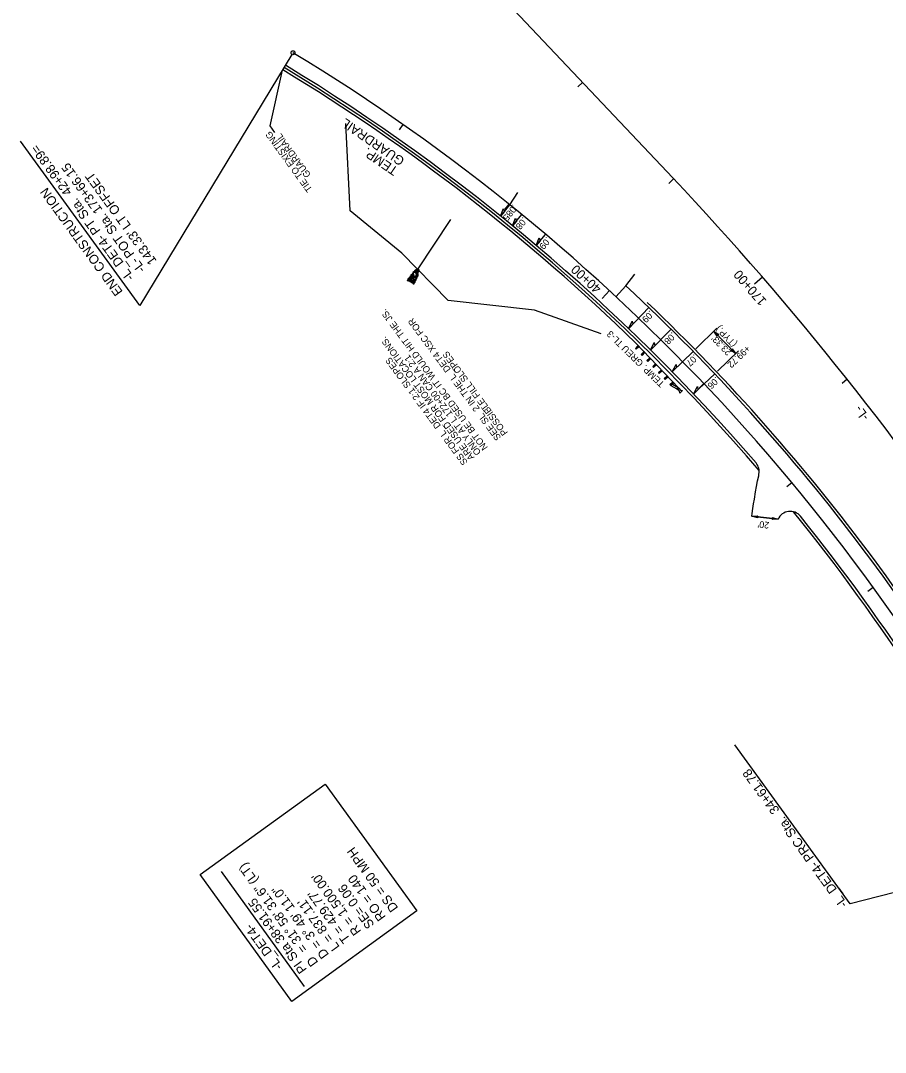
# Model space of a CAD drawing. Extents: x 473658 to 481584, y 489119 to 506230.
# Drawn here: x 474826 to 475478, y 502196 to 502974 of the extents above; entities that cross this region are included whole.
import ezdxf

# ---------------------------------------------------------------- set-up
doc = ezdxf.new("R2010")
doc.units = 0
for name, color, linetype in [('Exist Horizontal Alignment', 7, 'Continuous'), ('Prop Dimension', 7, 'Continuous'), ('Prop EOT', 7, 'Continuous'), ('Prop Guardrail', 7, 'Continuous'), ('Prop Guardrail Anchor Unit CELL', 7, 'Continuous'), ('Prop Horizontal Alignment', 7, 'Continuous'), ('Prop Horizontal Alignment Curve and Spiral Data', 7, 'Continuous'), ('Prop Horizontal Alignment Station Label', 7, 'Continuous'), ('Prop Horizontal Alignment Tick Label', 7, 'Continuous'), ('Prop Horizontal Alignment Tick Large', 7, 'Continuous'), ('Prop Horizontal Alignment Tick Small', 7, 'Continuous'), ('Prop Paved Shoulder', 7, 'Continuous'), ('Prop Superelevation  Arrow CELL', 7, 'Continuous'), ('Prop Superelevation Label', 7, 'Continuous'), ('Scratch_Level_3', 7, 'Continuous'), ('Scratch_Level_5', 7, 'Continuous'), ('Sheet Profile Grid Major CELL', 7, 'Continuous')]:
    doc.layers.add(name, color=color, linetype=linetype)

msp = doc.modelspace()

# ---------------------------------------------------------------- linework, layer by layer
at = {"layer": 'Exist Horizontal Alignment'}
for points in [[(475381.81, 502599.11), (475377.43, 502600.38), (475382.01, 502600.68), (475381.35, 502599.94)], [(475392.84, 502599.44), (475397.22, 502598.17), (475392.64, 502597.88), (475393.3, 502598.61)]]:
    msp.add_lwpolyline(points, close=True, dxfattribs=at)
at = {"layer": 'Prop Dimension'}
msp.add_line((475377.43, 502600.38), (475397.22, 502598.17), dxfattribs=at)
at = {"layer": 'Prop EOT'}
msp.add_line((475397.22, 502598.17), (475377.43, 502600.38), dxfattribs=at)
msp.add_lwpolyline([(475377.43, 502600.38), (475377.67, 502602.55), (475378.18, 502606.33), (475378.73, 502609.86), (475379.32, 502613.3), (475380.3, 502618.83), (475381.04, 502622.94), (475381.81, 502627), (475382.59, 502630.98), (475382.83, 502632.23)], dxfattribs=at)
for centre, radius, start, end in [((474253.94, 501667.1), 1489, 40.83118, 58.77708), ((474253.94, 501667.1), 1511, 26.80164, 47.10099), ((475373.01, 502634.11), 10, 349.13134, 40.83118), ((475406.36, 502594.11), 10, 38.81332, 156.02599), ((474253.94, 501667.1), 1489, 26.80164, 38.81332)]:
    msp.add_arc(centre, radius, start, end, dxfattribs=at)
at = {"layer": 'Prop Guardrail'}
msp.add_arc((474253.94, 501667.1), 1485, 45.75531, 58.77708, dxfattribs=at)
at = {"layer": 'Prop Guardrail Anchor Unit CELL'}
for p, q in [((475014.37, 502894.61), (475023.6, 502936.81)), ((475017.9, 502889.73), (475014.37, 502894.61)), ((475291.81, 502729.06), (475289.64, 502726.99)), ((475291.42, 502727.3), (475289.64, 502726.99)), ((475289.64, 502726.99), (475290.33, 502726.27)), ((475290.06, 502730.9), (475322.35, 502697.09)), ((475292.5, 502728.34), (475290.33, 502726.27)), ((475290.33, 502726.27), (475290.73, 502728.03)), ((475290.73, 502728.03), (475292.5, 502728.34)), ((475290.73, 502728.03), (475291.42, 502727.3)), ((475291.42, 502727.3), (475291.81, 502729.06)), ((475292.5, 502728.34), (475291.42, 502727.3)), ((475291.81, 502729.06), (475292.5, 502728.34)), ((475296.16, 502724.51), (475293.96, 502722.4)), ((475295.75, 502722.73), (475293.96, 502722.4)), ((475293.96, 502722.4), (475294.65, 502721.67)), ((475296.86, 502723.78), (475294.65, 502721.67)), ((475294.65, 502721.67), (475295.06, 502723.45)), ((475295.06, 502723.45), (475296.86, 502723.78)), ((475295.06, 502723.45), (475295.75, 502722.73)), ((475296.16, 502724.51), (475295.75, 502722.73)), ((475300.52, 502719.95), (475298.31, 502717.84)), ((475300.11, 502718.17), (475298.31, 502717.84)), ((475298.31, 502717.84), (475299, 502717.12)), ((475301.21, 502719.23), (475299, 502717.12)), ((475299, 502717.12), (475299.41, 502718.9)), ((475299.41, 502718.9), (475301.21, 502719.23)), ((475299.41, 502718.9), (475300.11, 502718.17)), ((475300.52, 502719.95), (475300.11, 502718.17)), ((475304.87, 502715.39), (475302.67, 502713.3)), ((475304.46, 502713.62), (475302.67, 502713.3)), ((475302.67, 502713.3), (475303.36, 502712.57)), ((475305.56, 502714.67), (475303.36, 502712.57)), ((475303.36, 502712.57), (475303.77, 502714.34)), ((475303.77, 502714.34), (475305.56, 502714.67)), ((475303.77, 502714.34), (475304.46, 502713.62)), ((475304.87, 502715.39), (475304.46, 502713.62)), ((475304.87, 502715.39), (475305.56, 502714.67)), ((475309.22, 502710.84), (475306.95, 502708.67)), ((475309.91, 502710.11), (475307.64, 502707.95)), ((475308.09, 502709.75), (475309.91, 502710.11)), ((475309.22, 502710.84), (475308.78, 502709.03)), ((475308.78, 502709.03), (475306.95, 502708.67)), ((475306.95, 502708.67), (475307.64, 502707.95)), ((475307.64, 502707.95), (475308.09, 502709.75)), ((475308.09, 502709.75), (475308.78, 502709.03)), ((475313.57, 502706.28), (475311.4, 502704.21)), ((475313.18, 502704.52), (475311.4, 502704.21)), ((475311.4, 502704.21), (475312.1, 502703.48)), ((475314.26, 502705.56), (475312.1, 502703.48)), ((475312.1, 502703.48), (475312.49, 502705.24)), ((475312.49, 502705.24), (475314.26, 502705.56)), ((475312.49, 502705.24), (475313.18, 502704.52)), ((475313.57, 502706.28), (475313.18, 502704.52)), ((475317.93, 502701.72), (475315.71, 502699.61)), ((475317.51, 502699.94), (475315.71, 502699.61)), ((475315.71, 502699.61), (475316.4, 502698.88)), ((475318.62, 502701), (475316.4, 502698.88)), ((475316.4, 502698.88), (475316.82, 502700.66)), ((475316.4, 502698.88), (475320.92, 502696.42)), ((475316.82, 502700.66), (475318.62, 502701)), ((475316.82, 502700.66), (475317.51, 502699.94)), ((475317.93, 502701.72), (475317.51, 502699.94)), ((475317.51, 502699.94), (475322, 502697.45)), ((475322, 502697.45), (475320.92, 502696.42)), ((475322.69, 502696.73), (475320.92, 502696.42)), ((475320.92, 502696.42), (475321.26, 502696.06)), ((475320.92, 502696.42), (475321.61, 502695.7)), ((475321.45, 502696.16), (475321.88, 502696.59)), ((475322.89, 502694.7), (475321.45, 502696.16)), ((475321.61, 502695.7), (475322, 502697.45)), ((475322.69, 502696.73), (475321.61, 502695.7)), ((475321.88, 502696.59), (475322.32, 502697.02)), ((475322.32, 502697.02), (475323.76, 502695.56)), ((475323.11, 502693.26), (475322.89, 502694.7)), ((475325.19, 502695.33), (475323.11, 502693.26)), ((475323.76, 502695.56), (475325.19, 502695.33))]:
    msp.add_line(p, q, dxfattribs=at)
at = {"layer": 'Prop Horizontal Alignment'}
msp.add_line((475317.78, 502855.51), (474915.81, 503280.98), dxfattribs=at)
for centre, radius, start, end in [((474253.94, 501667.1), 1500, 26.80164, 58.77708), ((473624.13, 501255.38), 2330, 23.81642, 43.37358)]:
    msp.add_arc(centre, radius, start, end, dxfattribs=at)
at = {"layer": 'Prop Horizontal Alignment Station Label'}
for p, q in [((475030.71, 502948.55), (474915.93, 502759.19)), ((474915.93, 502759.19), (474826.14, 502883.19)), ((475451.45, 502308.32), (475364.69, 502428.15)), ((475594.13, 502344.13), (475451.45, 502308.32)), ((475040.19, 502246), (474977.47, 502332.61))]:
    msp.add_line(p, q, dxfattribs=at)
msp.add_lwpolyline([(475030.67, 502234.65), (474961.46, 502330.23), (475055.64, 502398.42), (475124.85, 502302.84)], close=True, dxfattribs=at)
msp.add_circle((475031.49, 502949.83), 1.5, dxfattribs=at)
at = {"layer": 'Prop Horizontal Alignment Tick Large'}
for p, q in [((475385.52, 502780.63), (475379.47, 502775.4)), ((475270.02, 502770.54), (475264.6, 502764.65))]:
    msp.add_line(p, q, dxfattribs=at)
at = {"layer": 'Prop Horizontal Alignment Tick Small'}
for p, q in [((475249.78, 502927.49), (475246.14, 502924.06)), ((475114.31, 502895.82), (475111.44, 502891.72)), ((475318.45, 502854.8), (475314.82, 502851.37)), ((475194.25, 502835.77), (475191.12, 502831.88)), ((475449.34, 502703.66), (475445.42, 502700.55)), ((475341.27, 502700.4), (475337.64, 502696.95)), ((475407.69, 502625.66), (475403.84, 502622.47)), ((475468.98, 502546.68), (475464.93, 502543.74))]:
    msp.add_line(p, q, dxfattribs=at)
at = {"layer": 'Prop Paved Shoulder'}
for radius, start, end in [(1487, 40.59937, 58.77708), (1513, 26.80164, 46.33289), (1487, 26.80164, 39.04513)]:
    msp.add_arc((474253.94, 501667.1), radius, start, end, dxfattribs=at)
at = {"layer": 'Prop Superelevation  Arrow CELL'}
for points in [[(475188.05, 502826.57), (475190.24, 502832.5), (475190.94, 502830.18)], [(475197.04, 502819.27), (475199.28, 502825.18), (475199.96, 502822.85)], [(475214.84, 502804.46), (475217.17, 502810.34), (475217.82, 502808.01)], [(475284.47, 502741.78), (475287.16, 502747.5), (475287.66, 502745.13)], [(475351.36, 502736.23), (475348.8, 502740.01), (475352.51, 502737.31), (475351.54, 502737.16)], [(475301.06, 502725.62), (475303.85, 502731.29), (475304.31, 502728.91)], [(475362.7, 502726.69), (475365.26, 502722.91), (475361.54, 502725.62), (475362.52, 502725.76)], [(475317.4, 502709.21), (475320.28, 502714.84), (475320.7, 502712.45)], [(475333.48, 502692.54), (475336.44, 502698.13), (475336.82, 502695.73)]]:
    msp.add_lwpolyline(points, close=True, dxfattribs=at)
at = {"layer": 'Prop Superelevation Label'}
for p, q in [((475188.08, 502826.62), (475194.97, 502835.2)), ((475197.07, 502819.31), (475204.03, 502827.84)), ((475214.88, 502804.51), (475221.95, 502812.93)), ((475284.51, 502741.82), (475299.69, 502757.74)), ((475301.1, 502725.66), (475316.56, 502741.32)), ((475335.28, 502726.74), (475350.98, 502742.15)), ((475365.26, 502722.91), (475348.8, 502740.01)), ((475317.44, 502709.25), (475333.14, 502724.66)), ((475351.58, 502709.84), (475367.49, 502725.03)), ((475333.52, 502692.58), (475349.43, 502707.77))]:
    msp.add_line(p, q, dxfattribs=at)
at = {"layer": 'Scratch_Level_3'}
for p, q in [((475074.55, 502830.72), (475071.4, 502896.53)), ((475113.47, 502798.71), (475074.55, 502830.72)), ((475125.39, 502786.18), (475150.55, 502824.14)), ((475148.49, 502763.01), (475113.47, 502798.71)), ((475125.54, 502786.41), (475125.54, 502786.41)), ((475125.54, 502786.41), (475125.54, 502786.41)), ((475213.46, 502755.69), (475148.49, 502763.01)), ((475263.77, 502737.96), (475213.46, 502755.69))]:
    msp.add_line(p, q, dxfattribs=at)
for points in [[(475118.75, 502779.87), (475119.06, 502779.82), (475119.52, 502779.63), (475119.46, 502779.28), (475119.28, 502779.08), (475118.75, 502779.43), (475118.65, 502779.73), (475118.75, 502779.87)], [(475119.33, 502779.76), (475119.28, 502780.09), (475119.37, 502780.59), (475119.66, 502780.65), (475119.81, 502780.57), (475119.75, 502779.92), (475119.55, 502779.77), (475119.33, 502779.76)], [(475120.62, 502780.3), (475120.39, 502780.33), (475119.91, 502780.46), (475119.81, 502780.75), (475119.87, 502780.89), (475120.41, 502780.87), (475120.62, 502780.63), (475120.64, 502780.42)], [(475119.97, 502780.98), (475119.85, 502781.24), (475119.97, 502781.73), (475120.28, 502781.82), (475120.44, 502781.73), (475120.38, 502781.1), (475120.17, 502780.96), (475119.97, 502780.98)], [(475119.95, 502779.41), (475119.97, 502779.61), (475120.01, 502780.14), (475120.39, 502780.21), (475120.55, 502780.12), (475120.46, 502779.45), (475120.2, 502779.4), (475119.95, 502779.41)], [(475120.75, 502781.7), (475121.26, 502781.55), (475122.13, 502781.01), (475122.12, 502780.34), (475121.73, 502779.95), (475120.71, 502780.58), (475120.46, 502781.26), (475120.75, 502781.7)], [(475120.62, 502781.8), (475120.5, 502782.06), (475120.62, 502782.55), (475120.92, 502782.64), (475121.09, 502782.55), (475121.02, 502781.92), (475120.82, 502781.78), (475120.62, 502781.8)], [(475120.72, 502779.37), (475120.61, 502779.67), (475120.74, 502780.15), (475121.04, 502780.24), (475121.19, 502780.13), (475121.11, 502779.54), (475120.94, 502779.38), (475120.72, 502779.37)], [(475122.15, 502779.69), (475122.13, 502779.25), (475121.94, 502778.2), (475121.29, 502777.99), (475120.82, 502778.23), (475121.12, 502779.41), (475121.53, 502779.89), (475122.03, 502779.71)], [(475121.83, 502781.63), (475121.58, 502781.62), (475121.05, 502781.66), (475121.03, 502782.05), (475121.11, 502782.19), (475121.75, 502782.12), (475121.87, 502781.94), (475121.83, 502781.63)], [(475121.2, 502782.91), (475121.56, 502782.98), (475122.26, 502782.85), (475122.42, 502782.43), (475122.28, 502782.16), (475121.41, 502782.25), (475121.15, 502782.6), (475121.2, 502782.91)], [(475121.5, 502783.73), (475121.8, 502783.67), (475122.26, 502783.49), (475122.2, 502783.14), (475122.02, 502782.93), (475121.49, 502783.29), (475121.39, 502783.58), (475121.5, 502783.73)], [(475122.03, 502781.23), (475121.91, 502781.48), (475122.06, 502781.97), (475122.32, 502782.08), (475122.52, 502781.98), (475122.43, 502781.36), (475122.23, 502781.21), (475122.03, 502781.23)], [(475124.12, 502779.22), (475123.58, 502779.19), (475122.39, 502779.28), (475122.15, 502780.2), (475122.36, 502780.63), (475123.82, 502780.37), (475124.32, 502779.8), (475124.23, 502779.17)], [(475122.31, 502784.01), (475122.24, 502784.31), (475122.35, 502784.8), (475122.62, 502784.91), (475122.82, 502784.8), (475122.71, 502784.16), (475122.53, 502784.03), (475122.31, 502784.01)], [(475122.93, 502781.28), (475122.52, 502782.03), (475122.24, 502783.75), (475123.2, 502784.49), (475124.01, 502784.34), (475124.42, 502782.22), (475123.87, 502781.41), (475122.97, 502781.12)], [(475122.62, 502781.29), (475122.95, 502781.26), (475123.26, 502780.98), (475123.28, 502780.59), (475123.1, 502780.47), (475122.56, 502780.74), (475122.54, 502781.12), (475122.62, 502781.29)], [(475122.89, 502784.44), (475122.77, 502784.7), (475122.89, 502785.19), (475123.19, 502785.29), (475123.36, 502785.2), (475123.28, 502784.57), (475123.09, 502784.42), (475122.89, 502784.44)], [(475123.49, 502785.27), (475123.7, 502785.17), (475124.1, 502784.97), (475124.07, 502784.65), (475123.98, 502784.49), (475123.45, 502784.75), (475123.28, 502785.08), (475123.49, 502785.27)], [(475123.6, 502786.23), (475124.04, 502786.21), (475125.06, 502786.04), (475125.31, 502785.37), (475125.03, 502784.91), (475123.83, 502785.19), (475123.46, 502785.71), (475123.55, 502786.12)], [(475123.83, 502780.54), (475123.74, 502780.8), (475123.88, 502781.26), (475124.16, 502781.38), (475124.36, 502781.28), (475124.23, 502780.67), (475124.04, 502780.55), (475123.83, 502780.54)], [(475124.3, 502784.87), (475124.79, 502784.75), (475125.7, 502784.3), (475125.7, 502783.54), (475125.34, 502783.26), (475124.27, 502783.88), (475124.1, 502784.44), (475124.3, 502784.87)], [(475124.96, 502779.97), (475124.71, 502779.89), (475124.29, 502779.97), (475124.11, 502780.28), (475124.25, 502780.57), (475124.82, 502780.37), (475125.04, 502780.14), (475124.96, 502779.97)], [(475124.3, 502782.88), (475124.18, 502783.14), (475124.31, 502783.62), (475124.59, 502783.74), (475124.74, 502783.62), (475124.67, 502783.02), (475124.51, 502782.89), (475124.3, 502782.88)], [(475124.67, 502782.37), (475125.08, 502782.3), (475125.61, 502782.03), (475125.58, 502781.46), (475125.31, 502781.26), (475124.58, 502781.73), (475124.53, 502782.12), (475124.67, 502782.37)], [(475124.64, 502780.45), (475124.53, 502780.72), (475124.66, 502781.21), (475124.94, 502781.31), (475125.09, 502781.19), (475125.02, 502780.6), (475124.86, 502780.47), (475124.64, 502780.45)], [(475124.65, 502782.41), (475124.56, 502782.71), (475124.72, 502783.17), (475124.98, 502783.29), (475125.18, 502783.19), (475125.06, 502782.53), (475124.87, 502782.42), (475124.65, 502782.41)], [(475125.4, 502786.14), (475125.17, 502786.18), (475124.63, 502786.19), (475124.59, 502786.54), (475124.68, 502786.71), (475125.34, 502786.68), (475125.54, 502786.41), (475125.4, 502786.14)], [(475125.23, 502782.26), (475125.1, 502782.53), (475125.23, 502783.01), (475125.53, 502783.12), (475125.67, 502783), (475125.59, 502782.41), (475125.45, 502782.27), (475125.23, 502782.26)], [(475125.33, 502784.52), (475125.31, 502784.88), (475125.37, 502785.51), (475125.87, 502785.72), (475126.23, 502785.55), (475126, 502784.65), (475125.69, 502784.48), (475125.33, 502784.52)], [(475126.36, 502785.8), (475126.12, 502785.83), (475125.55, 502785.87), (475125.55, 502786.2), (475125.63, 502786.37), (475126.25, 502786.33), (475126.49, 502786.07), (475126.36, 502785.8)], [(475117.87, 502778.51), (475118.17, 502778.45), (475118.63, 502778.27), (475118.57, 502777.92), (475118.39, 502777.71), (475117.86, 502778.07), (475117.76, 502778.36), (475117.87, 502778.51)], [(475118.19, 502779.47), (475118.49, 502779.41), (475118.95, 502779.23), (475118.89, 502778.88), (475118.71, 502778.67), (475118.18, 502779.03), (475118.08, 502779.32), (475118.19, 502779.47)], [(475118.8, 502778.86), (475119.29, 502778.69), (475120.18, 502778.28), (475120.17, 502777.5), (475119.75, 502777.16), (475118.72, 502777.77), (475118.56, 502778.39), (475118.8, 502778.86)], [(475120.74, 502778.38), (475120.35, 502778.38), (475119.66, 502778.59), (475119.53, 502778.99), (475119.67, 502779.26), (475120.5, 502779.09), (475120.79, 502778.82), (475120.74, 502778.38)], [(475120.36, 502777.62), (475120.72, 502777.52), (475121.29, 502777.23), (475121.23, 502776.67), (475121.03, 502776.45), (475120.24, 502776.96), (475120.17, 502777.34), (475120.36, 502777.62)], [(475121.16, 502777.23), (475121.05, 502777.5), (475121.15, 502777.99), (475121.46, 502778.09), (475121.62, 502778), (475121.55, 502777.36), (475121.36, 502777.21), (475121.16, 502777.23)], [(475122.56, 502777.77), (475122.65, 502777.27), (475122.48, 502776.26), (475121.81, 502776.01), (475121.4, 502776.35), (475121.66, 502777.56), (475122.03, 502777.87), (475122.6, 502777.84)], [(475122.32, 502775.47), (475122.19, 502775.73), (475122.32, 502776.22), (475122.62, 502776.33), (475122.77, 502776.21), (475122.7, 502775.62), (475122.55, 502775.49), (475122.32, 502775.47)], [(475122.29, 502778.3), (475122.2, 502778.53), (475122.3, 502779.09), (475122.6, 502779.18), (475122.75, 502779.06), (475122.68, 502778.43), (475122.54, 502778.29), (475122.29, 502778.3)], [(475122.7, 502777.23), (475123.02, 502777.19), (475123.34, 502776.91), (475123.35, 502776.53), (475123.16, 502776.41), (475122.62, 502776.68), (475122.61, 502777.07), (475122.7, 502777.23)], [(475122.9, 502779.01), (475123.23, 502778.98), (475123.54, 502778.7), (475123.56, 502778.3), (475123.38, 502778.19), (475122.84, 502778.46), (475122.82, 502778.84), (475122.9, 502779.01)], [(475123.74, 502777.52), (475123.41, 502777.44), (475122.98, 502777.57), (475122.82, 502777.85), (475122.95, 502778.12), (475123.52, 502777.92), (475123.75, 502777.72), (475123.74, 502777.52)], [(475123.75, 502778.21), (475123.62, 502778.47), (475123.75, 502778.95), (475124.04, 502779.07), (475124.19, 502778.95), (475124.12, 502778.37), (475123.98, 502778.23), (475123.75, 502778.21)]]:
    msp.add_lwpolyline(points, dxfattribs=at)
at = {"layer": 'Scratch_Level_5'}
for p, q in [((475194.97, 502835.19), (475201.04, 502844.4)), ((475282.49, 502773.99), (475289.11, 502782.82)), ((475282.49, 502773.99), (475275, 502765.93))]:
    msp.add_line(p, q, dxfattribs=at)

# ---------------------------------------------------------------- texts
at = {"layer": 'Prop Dimension'}
msp.add_text("20'", height=5, rotation=173.63638, dxfattribs=at).set_placement((475390.75, 502595.98))
at = {"layer": 'Prop Guardrail Anchor Unit CELL'}
for s, rotation, p in [('TIE TO EXISTING', 125.90742, (475046.32, 502846.97)), ('GUARDRAIL', 125.90742, (475045.22, 502857.86)), ('TEMP. GREU TL-3', 135.68605, (475312, 502700.73))]:
    msp.add_text(s, height=5, rotation=rotation, dxfattribs=at).set_placement(p)
at = {"layer": 'Prop Horizontal Alignment Curve and Spiral Data'}
for s, p in [('DS = 50 MPH', (475111.11, 502305.15)), ('= 31%%d 58\' 31.6" (LT)', (475043.01, 502274.3)), ("R = 1,500.00'", (475083.19, 502287.52)), ('RO = 140', (475101.75, 502298.38)), ('SE= 0.06', (475093.22, 502292.52)), ('D = 3%%d 49\' 11.0"', (475058.89, 502269.93)), ("T = 429.77'", (475075.09, 502281.66)), ('PI Sta 38+91.55', (475042.3, 502258.74)), ("L = 837.11'", (475066.99, 502275.79)), ('D', (475050.79, 502264.06))]:
    msp.add_text(s, height=7, rotation=125.90742, dxfattribs=at).set_placement(p)
at = {"layer": 'Prop Horizontal Alignment Station Label'}
for s, rotation, p in [('-L_DET4- PT Sta.  42+98.89=', 125.93749, (474912.01, 502780.67)), ('-L- POT Sta. 173+66.15', 125.93749, (474920.52, 502786.84)), ("143.33' LT OFFSET", 125.93749, (474929.02, 502793)), ('END CONSTRUCTION', 125.93749, (474903.41, 502769.68)), ('-L-', 125.90742, (475466.25, 502675.43)), ('-L_DET4- PRC Sta.  34+61.78', 125.90742, (475449.87, 502308.14)), ('-L_DET4-', 125.90742, (475023.94, 502261.08))]:
    msp.add_text(s, height=7, rotation=rotation, dxfattribs=at).set_placement(p)
at = {"layer": 'Prop Horizontal Alignment Tick Label'}
for s, rotation, p in [('40+00', 137.39313, (475264.51, 502772.8)), ('170+00', 130.89059, (475388.96, 502762.91))]:
    msp.add_text(s, height=7, rotation=rotation, dxfattribs=at).set_placement(p)
at = {"layer": 'Prop Superelevation Label'}
for s, rotation, p in [('.085', 231.35267, (475197.46, 502835.96)), ('.08', 230.91315, (475204.83, 502826.33)), ('.09', 230.11301, (475222.71, 502811.39)), ('.09', 226.4831, (475300.57, 502755.94)), ('(TYP.)', 133.93021, (475366.57, 502730.75)), ('.08', 225.4701, (475317.43, 502739.52)), ("23.33'", 133.93021, (475362.55, 502724.41)), ('+99.72', 224.15413, (475373.37, 502729.67)), ('.07', 224.58452, (475334.07, 502722.93)), ('.06', 223.76453, (475350.25, 502705.94))]:
    msp.add_text(s, height=5, rotation=rotation, dxfattribs=at).set_placement(p)
at = {"layer": 'Scratch_Level_3'}
for s, p in [('NOT BE USED BC IT WOULD HIT THE JS.', (475178.59, 502652.31)), ('SEE SL_2 IN THE L_DET4 XSC FOR ', (475188.65, 502659.74)), ('ARE USED FOR MOST LOCATIONS. ', (475168.54, 502644.89)), ('SS FOR L_DET4 IF 2:1 SLOPES', (475163.51, 502641.17)), ('ONLY AT L 172+00 CAN A 2:1 ', (475173.56, 502648.6)), ('POSSIBLE FILL SLOPES', (475193.67, 502663.45))]:
    msp.add_text(s, height=5, rotation=126.44635, dxfattribs=at).set_placement(p)
at = {"layer": 'Sheet Profile Grid Major CELL'}
for s, p in [('GUARDRAIL', (475116.24, 502869.89)), ('TEMP. ', (475111.23, 502862.57))]:
    msp.add_text(s, height=7, rotation=145.59209, dxfattribs=at).set_placement(p)

doc.saveas('drawing.dxf')
